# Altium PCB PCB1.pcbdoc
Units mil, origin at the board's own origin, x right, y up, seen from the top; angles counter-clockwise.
Board outline 83910 x 42905 mil, 2 copper layers (Top Layer, Bottom Layer); 14 components, 17 nets, 60 pads, 2 vias.
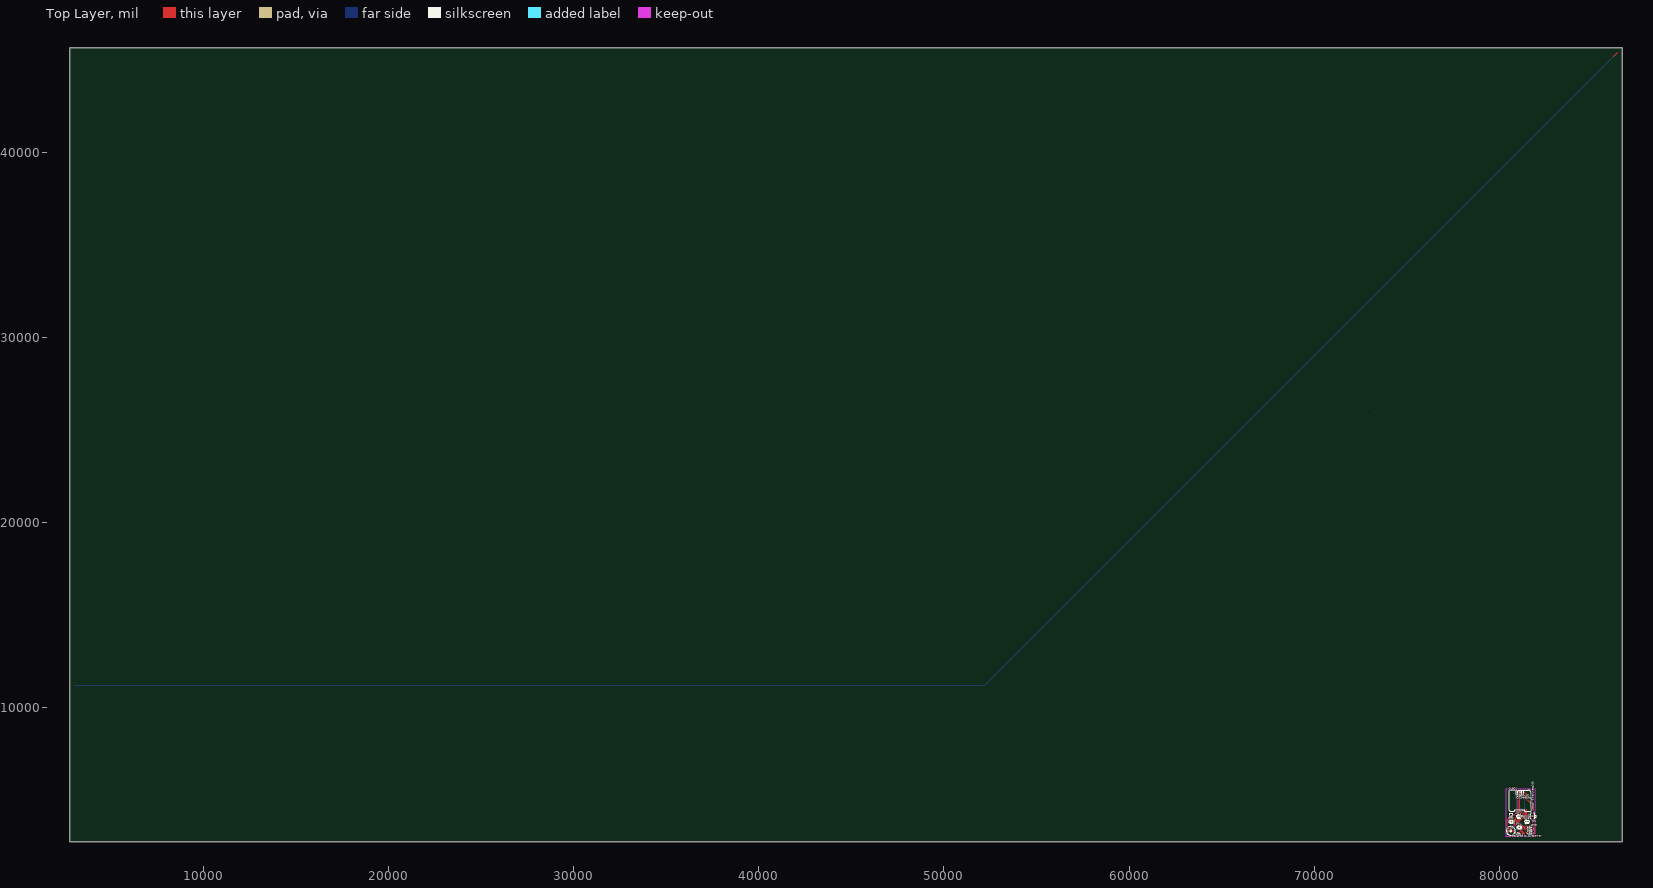
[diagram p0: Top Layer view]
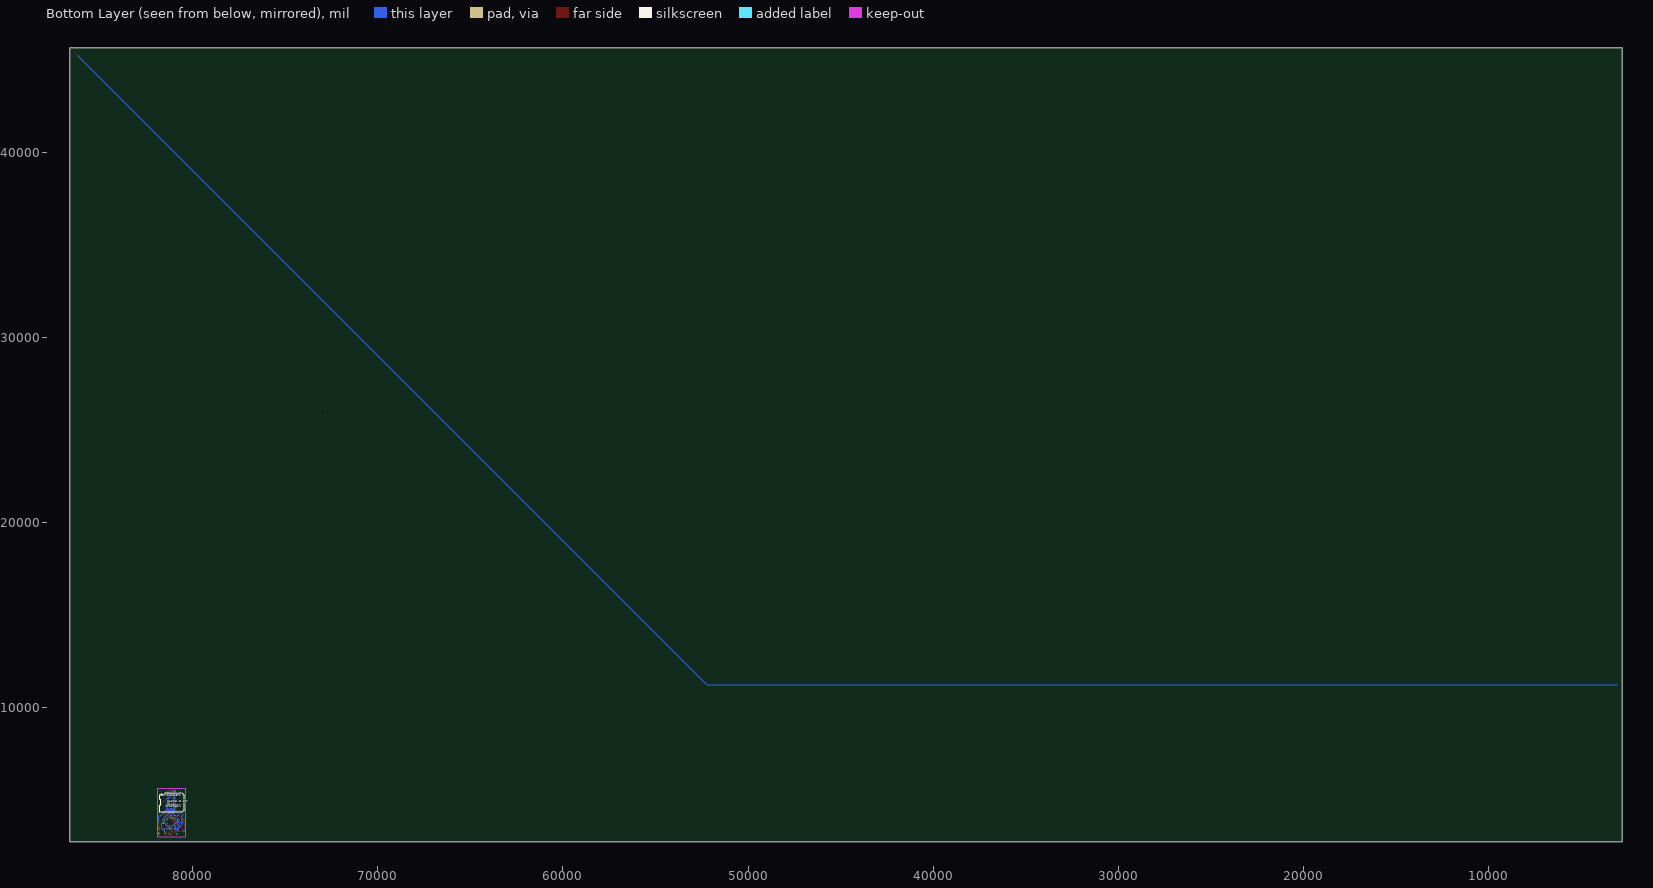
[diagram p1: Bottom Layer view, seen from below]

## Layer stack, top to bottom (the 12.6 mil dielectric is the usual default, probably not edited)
Top Layer: signal copper (thickness not stored)
Dielectric: dielectric 12.6, FR-4, Dk 4.8
Bottom Layer: signal copper (thickness not stored)

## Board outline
86660,2750 2750,2750 2750,45655 86660,45655

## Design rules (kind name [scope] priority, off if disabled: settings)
BoardOutlineClearance copperThickness1oz [All] p0: genericclearance=10 ignorepadtopadclearanceinfootprint=FALSE except(0: Arc-SplitContinuation Track-SplitContinuation SMDPad-SplitContinuation THPad-SplitContinuation Via-SplitContinuation Fill-SplitContinuation Poly-SplitContinuation Region-SplitContinuation Text-SplitContinuation; 6: Track-CutoutEdge SMDPad-CutoutEdge THPad-CutoutEdge Via-CutoutEdge Region-CutoutEdge; 11.8: Track-OutlineEdge SMDPad-OutlineEdge THPad-OutlineEdge Via-OutlineEdge Fill-OutlineEdge Region-OutlineEdge Poly-OutlineEdge Text-OutlineEdge Fill-CutoutEdge)
BoardOutlineClearance copperThickness2oz [All] p0: genericclearance=10 ignorepadtopadclearanceinfootprint=FALSE except(0: Arc-SplitContinuation Track-SplitContinuation SMDPad-SplitContinuation THPad-SplitContinuation Via-SplitContinuation Fill-SplitContinuation Poly-SplitContinuation Region-SplitContinuation Text-SplitContinuation; 6: Track-CutoutEdge SMDPad-CutoutEdge THPad-CutoutEdge Via-CutoutEdge Region-CutoutEdge; 11.8: Track-OutlineEdge SMDPad-OutlineEdge THPad-OutlineEdge Via-OutlineEdge Fill-OutlineEdge Region-OutlineEdge Poly-OutlineEdge Text-OutlineEdge Fill-CutoutEdge)
Clearance copperThickness1oz [(InNet('$1N1066') OR InNet('$1N1061') OR InNet('$1N1091') OR InNet('$1N1287') OR InNet('$1N1278') OR InNet('$1N1307') OR InNet('$1N1282') OR InNet('$1N1191') OR InNet('$1N1201') OR InNet('$1N1207') OR InNet('$1N1214') OR InNet('$1N1312') OR InNet('$1N2195') OR InNet('$1N2197') OR InNet('$1N2199') OR InNet('$1N2201') OR InNet('$1N2203'))] p1: gap=7 ignorepadtopadclearanceinfootprint=FALSE except(4: Track-Track; 6: Track-SMDPad SMDPad-SMDPad Track-THPad SMDPad-THPad THPad-THPad Track-Via SMDPad-Via THPad-Via Via-Via SMDPad-Fill THPad-Fill Via-Fill Fill-Fill Track-Region SMDPad-Region THPad-Region Via-Region Region-Region Track-Poly SMDPad-Poly THPad-Poly Via-Poly Fill-Poly Region-Poly Poly-Poly Track-Text SMDPad-Text THPad-Text Via-Text Fill-Text Region-Text Poly-Text Text-Text; 6.9: Track-Hole SMDPad-Hole THPad-Hole Via-Hole Fill-Hole Region-Hole Poly-Hole Text-Hole Sheet-Hole; 11.8: Track-Fill Fill-Region Track-Sheet SMDPad-Sheet THPad-Sheet Via-Sheet Fill-Sheet Region-Sheet Poly-Sheet Text-Sheet)
Clearance copperThickness2oz [All] p1: gap=7 ignorepadtopadclearanceinfootprint=FALSE except(6: Track-SMDPad SMDPad-SMDPad Track-THPad SMDPad-THPad THPad-THPad Track-Via SMDPad-Via THPad-Via Via-Via SMDPad-Fill THPad-Fill Via-Fill Fill-Fill Track-Region SMDPad-Region THPad-Region Via-Region Region-Region Track-Poly SMDPad-Poly THPad-Poly Via-Poly Fill-Poly Region-Poly Poly-Poly Track-Text SMDPad-Text THPad-Text Via-Text Fill-Text Region-Text Poly-Text Text-Text; 6.9: Track-Hole SMDPad-Hole THPad-Hole Via-Hole Fill-Hole Region-Hole Poly-Hole Text-Hole Sheet-Hole; 8: Track-Track; 11.8: Track-Fill Fill-Region Track-Sheet SMDPad-Sheet THPad-Sheet Via-Sheet Fill-Sheet Region-Sheet Poly-Sheet Text-Sheet)
DiffPairsRouting differentialPair [All] p1: maxuncoupledlength=10 minlimit=6 maxlimit=6 mostfreqgap=6 toplayer_minwidth=5 toplayer_prefwidth=10 toplayer_maxwidth=100 bottomlayer_minwidth=5 bottomlayer_prefwidth=10 bottomlayer_maxwidth=100
PasteMaskExpansion pasteMaskExpansion [All] p1: expansion=0
PlaneConnect innerPlane [All] p1: planeconnectstyle=Relief reliefexpansion=20 reliefentries=4 reliefconductorwidth=10 reliefairgap=10
PolygonConnect copperRegion [All] p1: connectstyle=Relief reliefentries=4 reliefconductorwidth=10 polygonreliefangle="90 Angle" airgapwidth=10
RoutingVias viaSize [All] p1: viastyle="Through Hole" holewidth=12.0078 minholewidth=11.811 maxholewidth=248.0314 width=24.0158 minwidth=19.685 maxwidth=393.7008
SolderMaskExpansion solderMaskExpansion [All] p1: useseparateexpansions=TRUE expansion=2 expansionbottom=2
Width copperThickness1oz [All] p1: maxlimit=100 minlimit=5 preferedwidth=10
Width copperThickness2oz [All] p1: maxlimit=100 minlimit=8 preferedwidth=10

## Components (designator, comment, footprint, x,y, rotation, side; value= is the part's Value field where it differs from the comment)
OLED1 "0.96OLED_4P_MODULE_JX" 0.96OLED_4P 81115,5475 r0 top
Q1 "BC547B_C719806" TO-92-3_L4.9-W3.7-P1.27-L 80635,4215 r180 top
R1 "resistor" "Resistor 1/8w 7mm metal film" 81480,3525 r0 top
R2 "resistor" "Resistor 1/8w 7mm metal film" 81485,3410 r0 top
R3 "resistor" "Resistor 1/8w 7mm metal film" 81490,3290 r0 top
R4 "resistor" "Resistor 1/8w 7mm metal film" 81485,3165 r0 top
R5 "resistor" "Resistor 1/8w 7mm metal film" 80865,3155 r0 top
SW1 "MLD-TS-6X6X5-J" SW-TH_4P-L6.0-W6.0-P4.50-LS6.5 81075,4115 r0 top
SW2 "MLD-TS-6X6X5-J" SW-TH_4P-L6.0-W6.0-P4.50-LS6.5 80660,3825 r0 top
SW3 "MLD-TS-6X6X5-J" SW-TH_4P-L6.0-W6.0-P4.50-LS6.5 81505,3835 r0 top
SW4 "MLD-TS-6X6X5-J" SW-TH_4P-L6.0-W6.0-P4.50-LS6.5 81090,3525 r0 top
SW5 "SK12D07VG4" SW-TH_SK12D07VG4 81810,4135 r90 top
U1 "_x001F_BEEF-12095" BUZ-TH_BD12.0-P7.60-D0.6-FD 80635,3330 r0 top
"wemos d1 mini" "WEMOS D1 MINI" "WEMOS D1 MINI" 81465,5305 r180 bottom

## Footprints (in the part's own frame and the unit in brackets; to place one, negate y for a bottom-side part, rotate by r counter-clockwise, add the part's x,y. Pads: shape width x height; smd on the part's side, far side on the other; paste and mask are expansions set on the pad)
0.96OLED_4P [mm]
  round 1.65 hole 1 copper offset 0,0: 1(-3.81,-0.001) 2(-1.27,0.002) 3(1.27,0.002) 4(3.81,0.002)
  silkscreen extent -15,-27.5 15,1.5
BUZ-TH_BD12.0-P7.60-D0.6-FD [mm]
  round 1.8 hole 1: 1(-3.8,0) 2(3.8,0)
  silkscreen extent -6,-6 6,6
"Resistor 1/8w 7mm metal film" [mm]
  round 2 hole 0.9: 1(0,0) 2(9,0)
  silkscreen extent 1.39,-1 7.64,1
SW-TH_4P-L6.0-W6.0-P4.50-LS6.5 [mm]
  round 1.8 hole 1.2: 1(-3.25,2.25) 2(3.25,2.25) 3(-3.25,-2.25) 4(3.25,-2.25)
  silkscreen extent -3,-3 3,3
SW-TH_SK12D07VG4 [mil]
  round 60 hole 36: 1(-78.74,0) 2(0,0) 3(78.74,0)
  oval 55.12x86.61 hole 31.5 slot 62.99 at 90 deg: 4(163.38,0) 5(-163.39,0)
  silkscreen extent -171,-191 171,87
TO-92-3_L4.9-W3.7-P1.27-L [mm]
  rect 0.9x1.6 hole 0.7: 1(-1.27,0)
  oval 0.9x1.6 hole 0.7: 2(0,0) 3(1.27,0)
  silkscreen extent -2.48,-1.5 2.48,2.48
"WEMOS D1 MINI" [mil]
  round 60 hole 36: 1(0,-899.99) 2(100,-899.99) 3(200,-899.99) 4(300,-899.99) 5(400,-899.99) 6(500,-899.99) 7(600,-899.99) 8(700,-899.99) 9(700,0.01) 10(600,0.01) 11(500,0.01) 12(400,0.01) 13(300,0.01) 14(200,0.01) 15(100,0.01) 16(0,0.01)
  silkscreen extent -354,-954 1000,54

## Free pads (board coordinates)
  round 60 hole 0.1: 1(81770,5495) 1(81860,3710) 2(80450,3070) 2(81860,3805)

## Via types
v1: diameter 24.02, hole 12.01, Top Layer to Bottom Layer, 2 vias

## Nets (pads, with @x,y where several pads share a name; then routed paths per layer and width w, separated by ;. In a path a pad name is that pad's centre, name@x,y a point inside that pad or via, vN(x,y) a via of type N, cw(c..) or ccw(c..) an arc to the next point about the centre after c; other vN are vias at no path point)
$1N1061: "wemos d1 mini.6" OLED1.3 | length 1473.6
  Bottom Layer w10: 80965,4405 80965,5247.04 81005.99,5288.03 81005.99,5372.5 80921.54,5456.95 80921.54,5492.95 80947,5518.41 80983,5518.41 81008.46,5492.95 81008.46,5451.31 81029.79,5429.98 81119.93,5429.98 OLED1.3@81165,5475.05
$1N1066: "wemos d1 mini.5" OLED1.4 | length 1687.5
  Bottom Layer w10: 81065,4405 81205.98,4545.99 81324.02,4427.95 81324.02,4388.03 81348.02,4364.02 81381.98,4364.02 81405.99,4388.03 81405.99,4421.98 81379.02,4448.95 81379.02,5080.75 81265,5194.77 81265,5247.04 81224.02,5288.03 81224.02,5321.98 81265,5362.96 OLED1.4@81265,5475.05
$1N1091: "wemos d1 mini.16" OLED1.2 pad.1@81770,5495 pad.2@81860,3805 R1.2 R2.2 R3.2 R4.2 SW5.2 | length 3503.4
  Top Layer w10: 81465,5305 81338.42,5431.59 81147,5431.59 81103.53,5475.05 81065,5475.05 81065,5470.05 81219.02,5316.03 81219.02,5288.03 81859.29,4647.75 81859.29,4319.36 81864.29,4314.36 81864.29,4282.42 81859.29,4277.42 81859.29,3992.58 81864.29,3987.58 81864.29,3955.64 81859.29,3950.64 81859.29,3934.29 81815,3890 81815,3429.33 81834.33,3410 R2.2 R4.2
  Bottom Layer w10: SW5.2 81864.29,4080.71 81864.29,3867.25 81860,3862.96 pad.2@81860,3805
$1N1191: "wemos d1 mini.13" SW1.1 | length 1211.8
  Top Layer w10: SW1.1 81125,4381.53 81125,4387.04 81124.02,4388.03 81124.02,4421.98 81125,4422.96 81125,5297.93 81132.07,5305 81165,5305
$1N1201: "wemos d1 mini.14" SW2.1 | length 2771.3
  Top Layer w10: SW2.1 81021.54,4403.07 81021.54,5493.05 81047,5518.51 81283,5518.51 81308.46,5493.05 81308.46,5457.05 81319.91,5445.6 81344.22,5445.6 81443.84,5345.99 81481.98,5345.99 81505.99,5321.98 81505.99,5288.03 81481.98,5264.02 81448.02,5264.02 81424.02,5288.03 81424.02,5321.98 81356.71,5389.29 81272.43,5305 81265,5305
$1N1207: SW3.1
$1N1214: "wemos d1 mini.4" SW4.1 | length 2161.1
  Bottom Layer w10: SW4.1 80962.05,3502.06 81008.47,3455.65 81008.47,3417.19 80981.28,3390 80979.98,3390 80954.98,3365 80885.18,3365 80592.28,3657.9 80592.28,4153.35 80556.3,4189.33 80556.3,4240.67 80573.11,4257.48 80707.27,4257.48 80807.58,4157.16 80966.28,4157.16 81165,4355.89 81165,4405
$1N1278: Q1.2 R5.2 | length 2179.2
  Top Layer w10: Q1.2 80635,4102 80424.96,3891.96 80424.96,3304.97 80460.36,3269.57 80510.43,3269.57 80556.84,3315.98 80732.98,3315.98 80765.38,3283.58 81240.75,3283.58 81362.92,3161.41 81225.74,3161.41 R5.2
$1N1282: "wemos d1 mini.3" R5.1 | length 4226.2
  Top Layer w10: R5.1 80979.57,3269.57 81033.55,3269.57 81198.47,3104.65 81240.19,3104.65 81282.94,3147.4 81368.72,3147.4 81376.93,3155.61 81376.93,3167.22 81246.55,3297.6 81190.23,3297.6 80865,3622.83 81505.99,4263.81 81505.99,4421.98 81481.98,4445.99 81448.02,4445.99 81424.02,4421.98 81424.02,4332.95 80900.63,3809.57 80900.63,4045.65 80927.82,4072.84 80932.84,4072.84 81017.16,4157.16 81222.18,4157.16 81249.37,4184.35 81249.37,4389.37 81265,4405
$1N1287: Q1.3 SW4.3 | length 1010
  Bottom Layer w10: Q1.3 80606.3,4193.7 80606.3,3852.43 80820,3638.73 80820,3450 80827.07,3442.93 80955.54,3442.93 SW4.3
$1N1307: Q1.1 U1.2 | length 1404.8
  Top Layer w10: Q1.1 80685,4093.72 80551.28,3960 80512.82,3960 80438.98,3886.15 80438.98,3310.77 80466.17,3283.58 80504.62,3283.58 80551.04,3330 U1.2
$1N1312: "wemos d1 mini.1" SW5.1 U1.1 | length 2037.2
  Top Layer w10: U1.1 81156.53,4001.14 81156.53,4045.65 81183.72,4072.84 81228.23,4072.84 81465,4309.61 81465,4405
  Bottom Layer w10: 81465,4405 81810,4060 SW5.1 ; 81469.41,4405 81494.78,4430.37 81497.6,4430.37
$1N2195: "wemos d1 mini.2" OLED1.1 pad.1@81860,3710 SW1.4 SW2.4 SW3.4 SW4.4 | length 8039.9
  Top Layer w10: SW4.4 81217.95,3547.94 81171.53,3594.35 81171.53,3632.81 81198.72,3660 81237.18,3660 81422.53,3474.65 81745.19,3474.65 81788.98,3430.86 81788.98,3389.14 81823.47,3354.65 81823.47,3340.35 81793.98,3310.86 81793.98,3269.14 81818.47,3244.65 81818.47,3215.35 81788.98,3185.86 81788.98,3144.14 81818.47,3114.65 81860.19,3114.65 81889.68,3144.14 81889.68,3185.86 81865.19,3210.35 81865.19,3239.65 81894.68,3269.14 81894.68,3310.86 81860.19,3345.35 81860.19,3359.65 81889.68,3389.14 81889.68,3430.86 81855.19,3465.35 81855.19,3474.65 81884.68,3504.14 81884.68,3545.86 81860,3570.54 pad.1@81860,3710
  Bottom Layer w10: SW2.4 80787.95,3847.94 80741.53,3894.35 80741.53,3932.81 80768.72,3960 80986.56,3960 ; OLED1.1 81124.02,5315.93 81124.02,5288.03 81148.02,5264.02 81175.93,5264.02 81365,5074.95 81365,4416.96 ; SW4.4 81527.95,3746.42 SW3.4 81352.95,4026.42 SW1.4 81077.95,4026.42 81011.53,3960 80986.56,3960 ; 81365,4405 81365,4416.96 ; 80986.56,3960 81156.53,4129.97 81156.53,4222.81 81224.02,4290.29 81224.02,4411.24 81167.45,4467.81 81120,4420.36 81120,4382.22 81087.78,4350 81042.22,4350 81010,4382.22 81010,5225.99 81024.02,5240.01 81024.02,5321.98 81048.02,5345.99 81081.98,5345.99 81105.99,5321.98 81105.99,5283.84 81354.83,5035 81354.83,4427.13 81365,4416.96
$1N2197: R1.1 SW1.2 | length 1506.5
  Top Layer w10: SW1.2 81202.95,4366.96 81224.02,4388.03 81224.02,4421.98 81248.02,4445.99 81281.98,4445.99 81305.99,4421.98 81324.02,4421.98 81348.02,4445.99 81381.98,4445.99 81400.18,4427.78 81410,4427.78 81442.22,4460 81487.78,4460 81520,4427.78 81520,3784.29 81480,3744.29 R1.1
$1N2199: R2.1 SW2.2 | length 997
  Bottom Layer w10: SW2.2 81171.53,3530 81171.53,3417.19 81198.72,3390 81237.18,3390 81260.6,3413.43 81273.89,3413.43 81281,3420.53 81291.53,3410 R2.1
$1N2201: "wemos d1 mini.12" R3.1 SW3.2 | length 2686.9
  Bottom Layer w10: 81065,5305 81065,4462.96 81024.02,4421.98 81024.02,4388.03 81048.02,4364.02 81081.98,4364.02 81105.99,4388.03 81105.99,4426.17 81161.64,4481.82 81173.25,4481.82 81209.09,4445.99 81281.98,4445.99 81305.99,4421.98 81305.99,4284.01 81632.95,3957.05 SW3.2 81632.95,3812.06 81679.37,3765.65 81679.37,3479.37 R3.1
$1N2203: R4.1 SW4.2 | length 559.2
  Top Layer w10: SW4.2 81434.65,3396.88 81434.65,3274.14 81485,3223.79 R4.1
pads on no net: "wemos d1 mini.7" "wemos d1 mini.8" "wemos d1 mini.9" "wemos d1 mini.10" "wemos d1 mini.11" "wemos d1 mini.15" SW1.3 SW2.3 SW3.3 SW5.3 SW5.4 SW5.5
copper on no net: | length 97566.1
  Top Layer w10: v1(86205,45200) 86405,45400
  Bottom Layer w10: 3005,11200 52205,11200 v1(86205,45200)
  other v1: 73005,25930

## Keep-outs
Board Outline Layer:
  lines w10: 80375,3000 81920,3000 81920,5610 80375,5610 80375,3000

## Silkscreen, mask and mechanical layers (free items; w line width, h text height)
Top Silkscreen Layer:
  text "Github- @sasukeop108" at 81885,4405 h75 r90
  text "ClockX-V1" at 81210,4070 h100
  text "vcc" at 81760,3815 h100
  text "GND" at 81735,3590 h100
  text "designed by sivasankar" at 80720,3005 h100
